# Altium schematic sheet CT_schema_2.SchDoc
size 461 x 327 mm
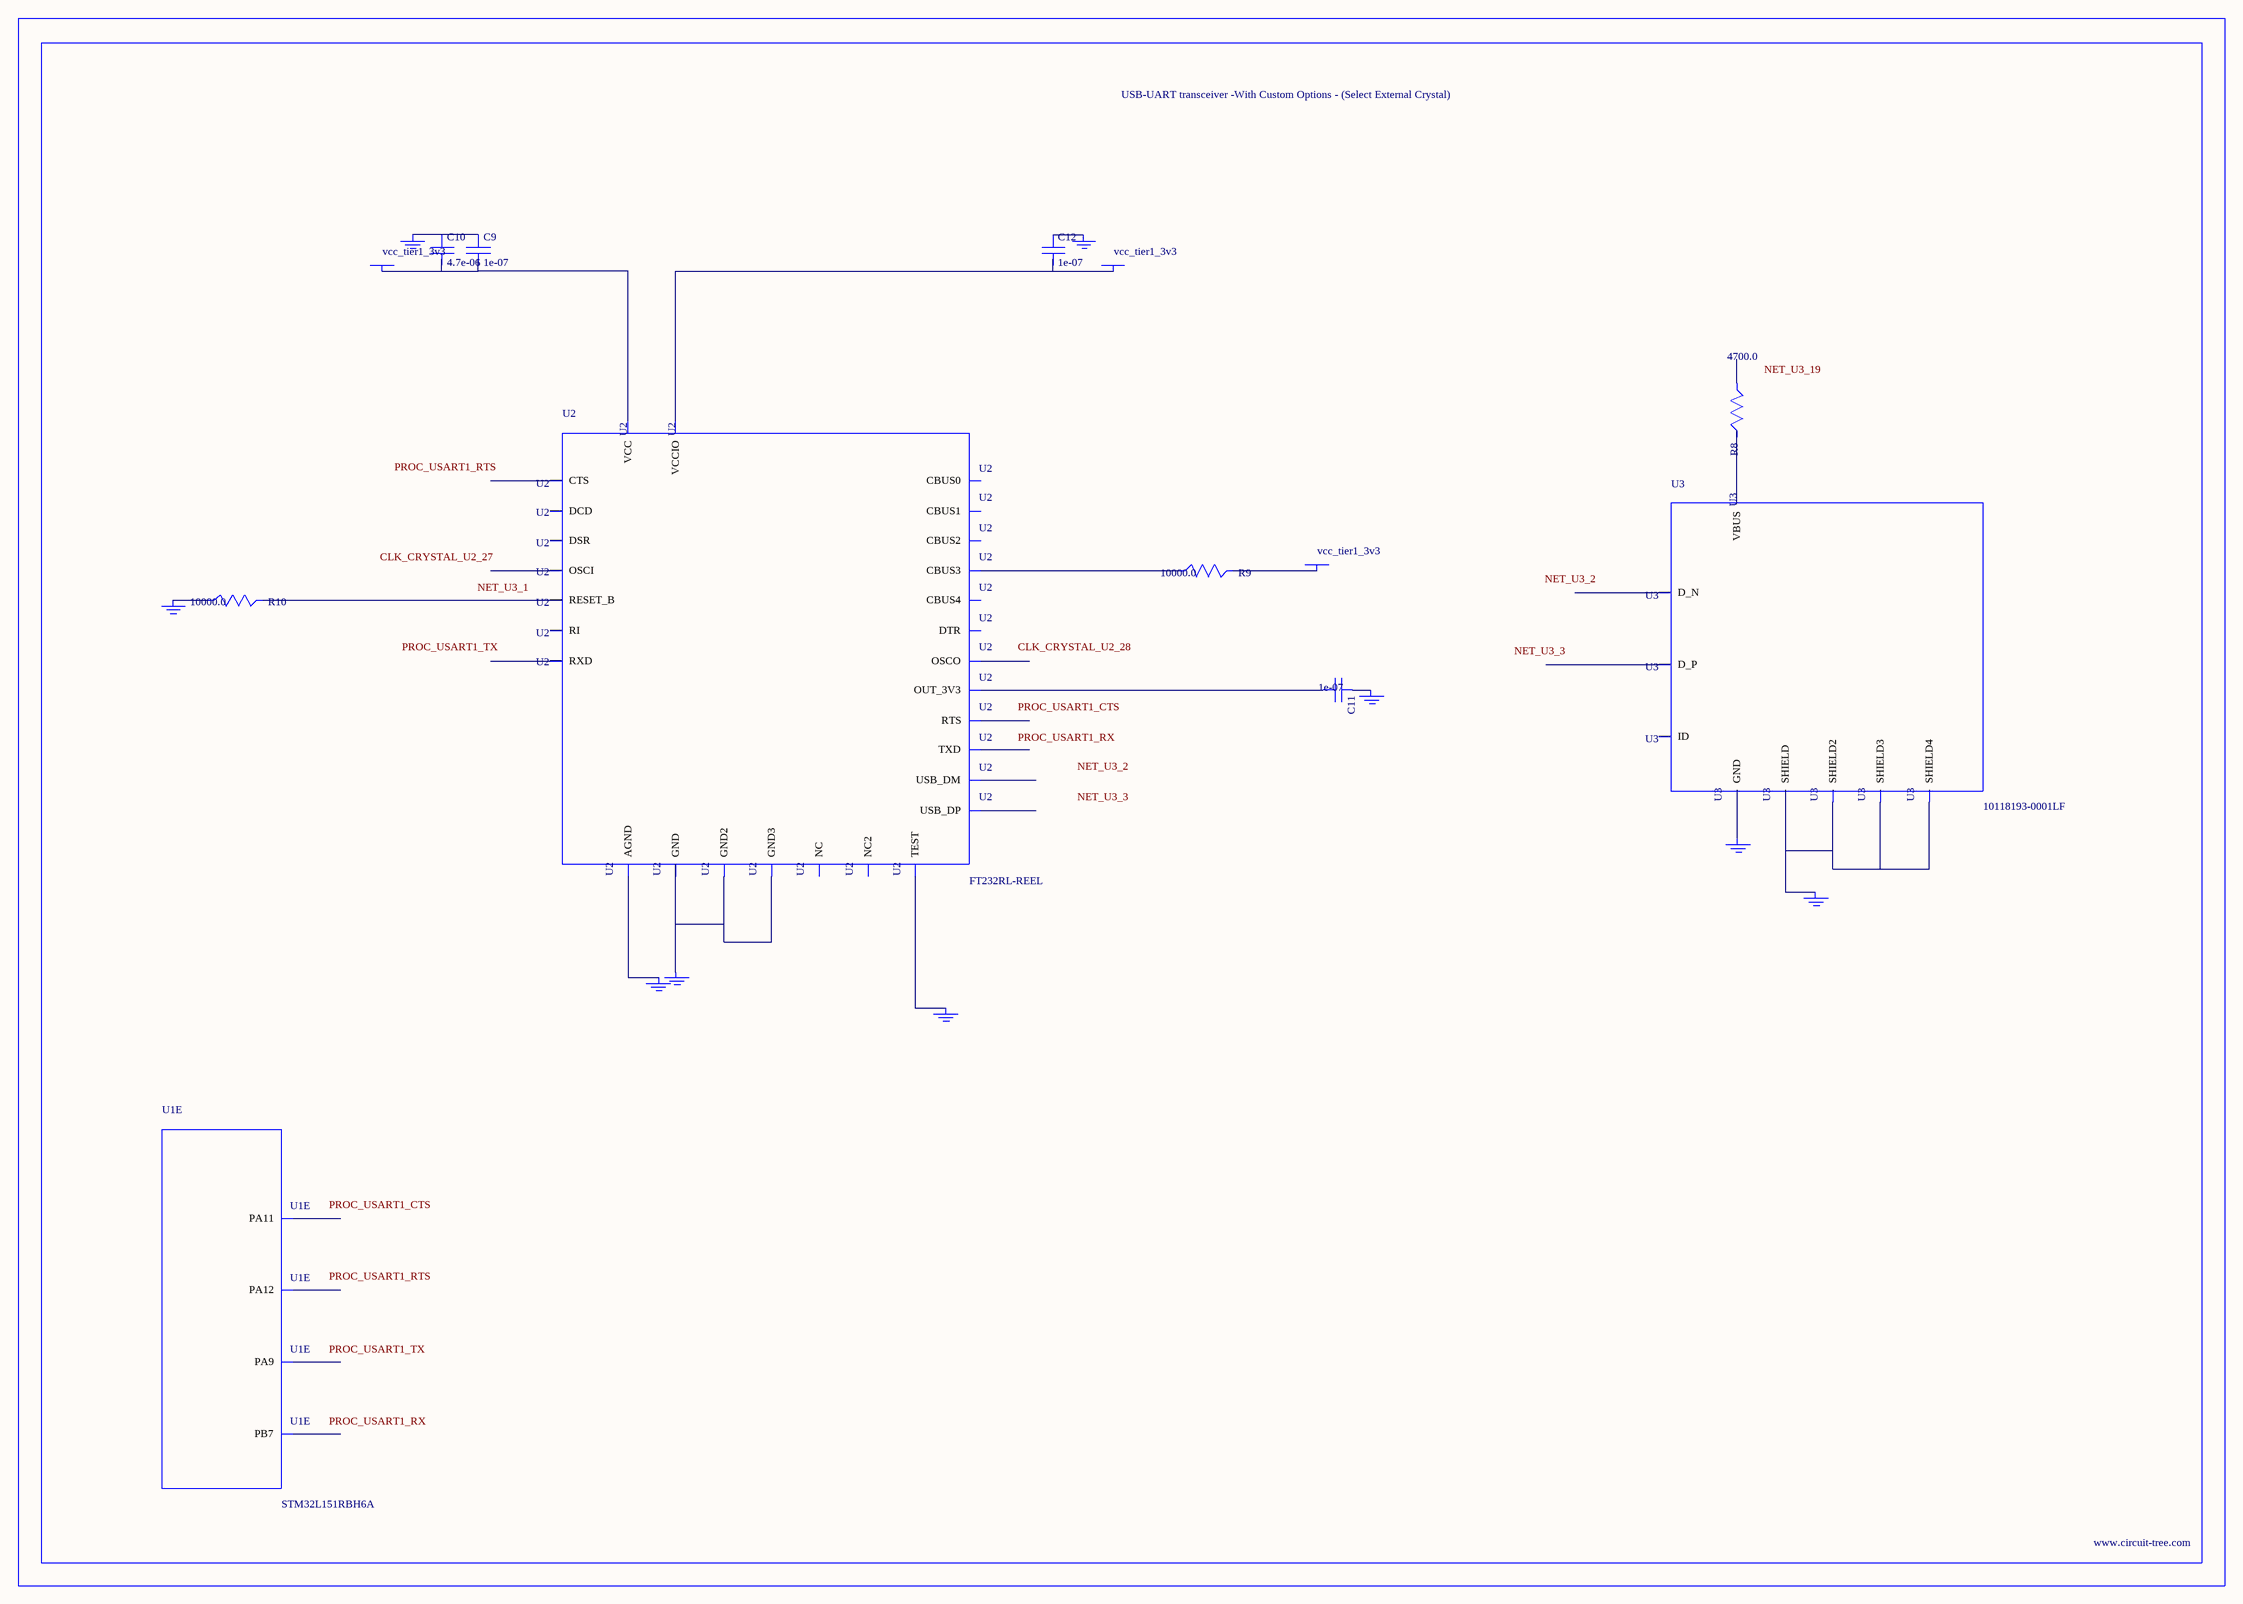
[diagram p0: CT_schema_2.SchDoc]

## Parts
BORDER1  (no value)
C9  1e-07  [C0402]
C10  4.7e-06  [C0805]
C11  1e-07  [C0402]
C12  1e-07  [C0402]
GND_INSTANCE_1_0  (no value)
GND_INSTANCE_1_1  (no value)
GND_INSTANCE_1_2  (no value)
GND_INSTANCE_1_3  (no value)
GND_INSTANCE_1_4  (no value)
GND_INSTANCE_1_5  (no value)
GND_INSTANCE_1_6  (no value)
GND_INSTANCE_1_7  (no value)
GND_INSTANCE_1_8  (no value)
POWER_INSTANCE_1_0  vcc_tier1_3v3
POWER_INSTANCE_1_1  vcc_tier1_3v3
POWER_INSTANCE_1_2  vcc_tier1_3v3
R8  4700.0  [R0603]
R9  10000.0  [R0603]
R10  10000.0  [R0603]
U1  STM32L151RBH6A  [TFBGA64]  (part E of 6)
U2  FT232RL-REEL  [SSOP-28]
U3  10118193-0001LF  [FCI_10118193-0001LF]

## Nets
NetC9_1: C9.1 C10.1 GND_INSTANCE_1_3.0(GND)
NetC9_2: C9.2 C10.2 POWER_INSTANCE_1_2.0(PWR) U2.20(VCC)
NetC11_1: C11.1 GND_INSTANCE_1_1.0(GND)
NetC11_2: C11.2 U2.17(OUT_3V3)
NetC12_1: C12.1 GND_INSTANCE_1_0.0(GND)
NetC12_2: C12.2 POWER_INSTANCE_1_0.0(PWR) U2.4(VCCIO)
NetGND_INSTANCE_1_2_0: GND_INSTANCE_1_2.0(GND) R10.1
NetGND_INSTANCE_1_4_0: GND_INSTANCE_1_4.0(GND) U2.25(AGND)
NetGND_INSTANCE_1_5_0: GND_INSTANCE_1_5.0(GND) U2.26(TEST)
NetGND_INSTANCE_1_6_0: GND_INSTANCE_1_6.0(GND) U2.7(GND) U2.18(GND2) U2.21(GND3)
NetGND_INSTANCE_1_7_0: GND_INSTANCE_1_7.0(GND) U3.6(SHIELD) U3.7(SHIELD2) U3.8(SHIELD3) U3.9(SHIELD4)
NetGND_INSTANCE_1_8_0: GND_INSTANCE_1_8.0(GND) U3.5(GND)
NetPOWER_INSTANCE_1_1_0: POWER_INSTANCE_1_1.0(PWR) R9.2
NetR8_2: R8.2 U3.1(VBUS)
NetR9_1: R9.1 U2.14(CBUS3)
NetR10_2: R10.2 U2.19(RESET_B)

Not connected (* = marked no-connect by the designer): R8 1; U1 B8(PA12) C3(PB7) C7(PA9) C8(PA11); U2 1(TXD) 2(DTR) 3(RTS) 5(RXD) 6(RI) 8(NC) 9(DSR) 10(DCD) 11(CTS) 12(CBUS4) 13(CBUS2) 15(USB_DP) 16(USB_DM) 22(CBUS1) 23(CBUS0) 24(NC2) 27(OSCI) 28(OSCO); U3 2(D_N) 3(D_P) 4(ID)

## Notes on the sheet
- Labels drawn without touching a wire or pin: CLK_CRYSTAL_U2_27, CLK_CRYSTAL_U2_28, NET_U3_1, NET_U3_2, NET_U3_3, NET_U3_19, PROC_USART1_CTS, PROC_USART1_RTS, PROC_USART1_RX, PROC_USART1_TX

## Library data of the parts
BORDER1 = BORDER_PAGE1
C9 C11 C12 = C0402C104K3RACTU
C10 = C0805C475K4RACTU
GND_INSTANCE_1_0-GND_INSTANCE_1_8 = GND
POWER_INSTANCE_1_0-POWER_INSTANCE_1_2 = PWR
R8 = RC0603JR-074K7L
R9 R10 = RC0603JR-0710KL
